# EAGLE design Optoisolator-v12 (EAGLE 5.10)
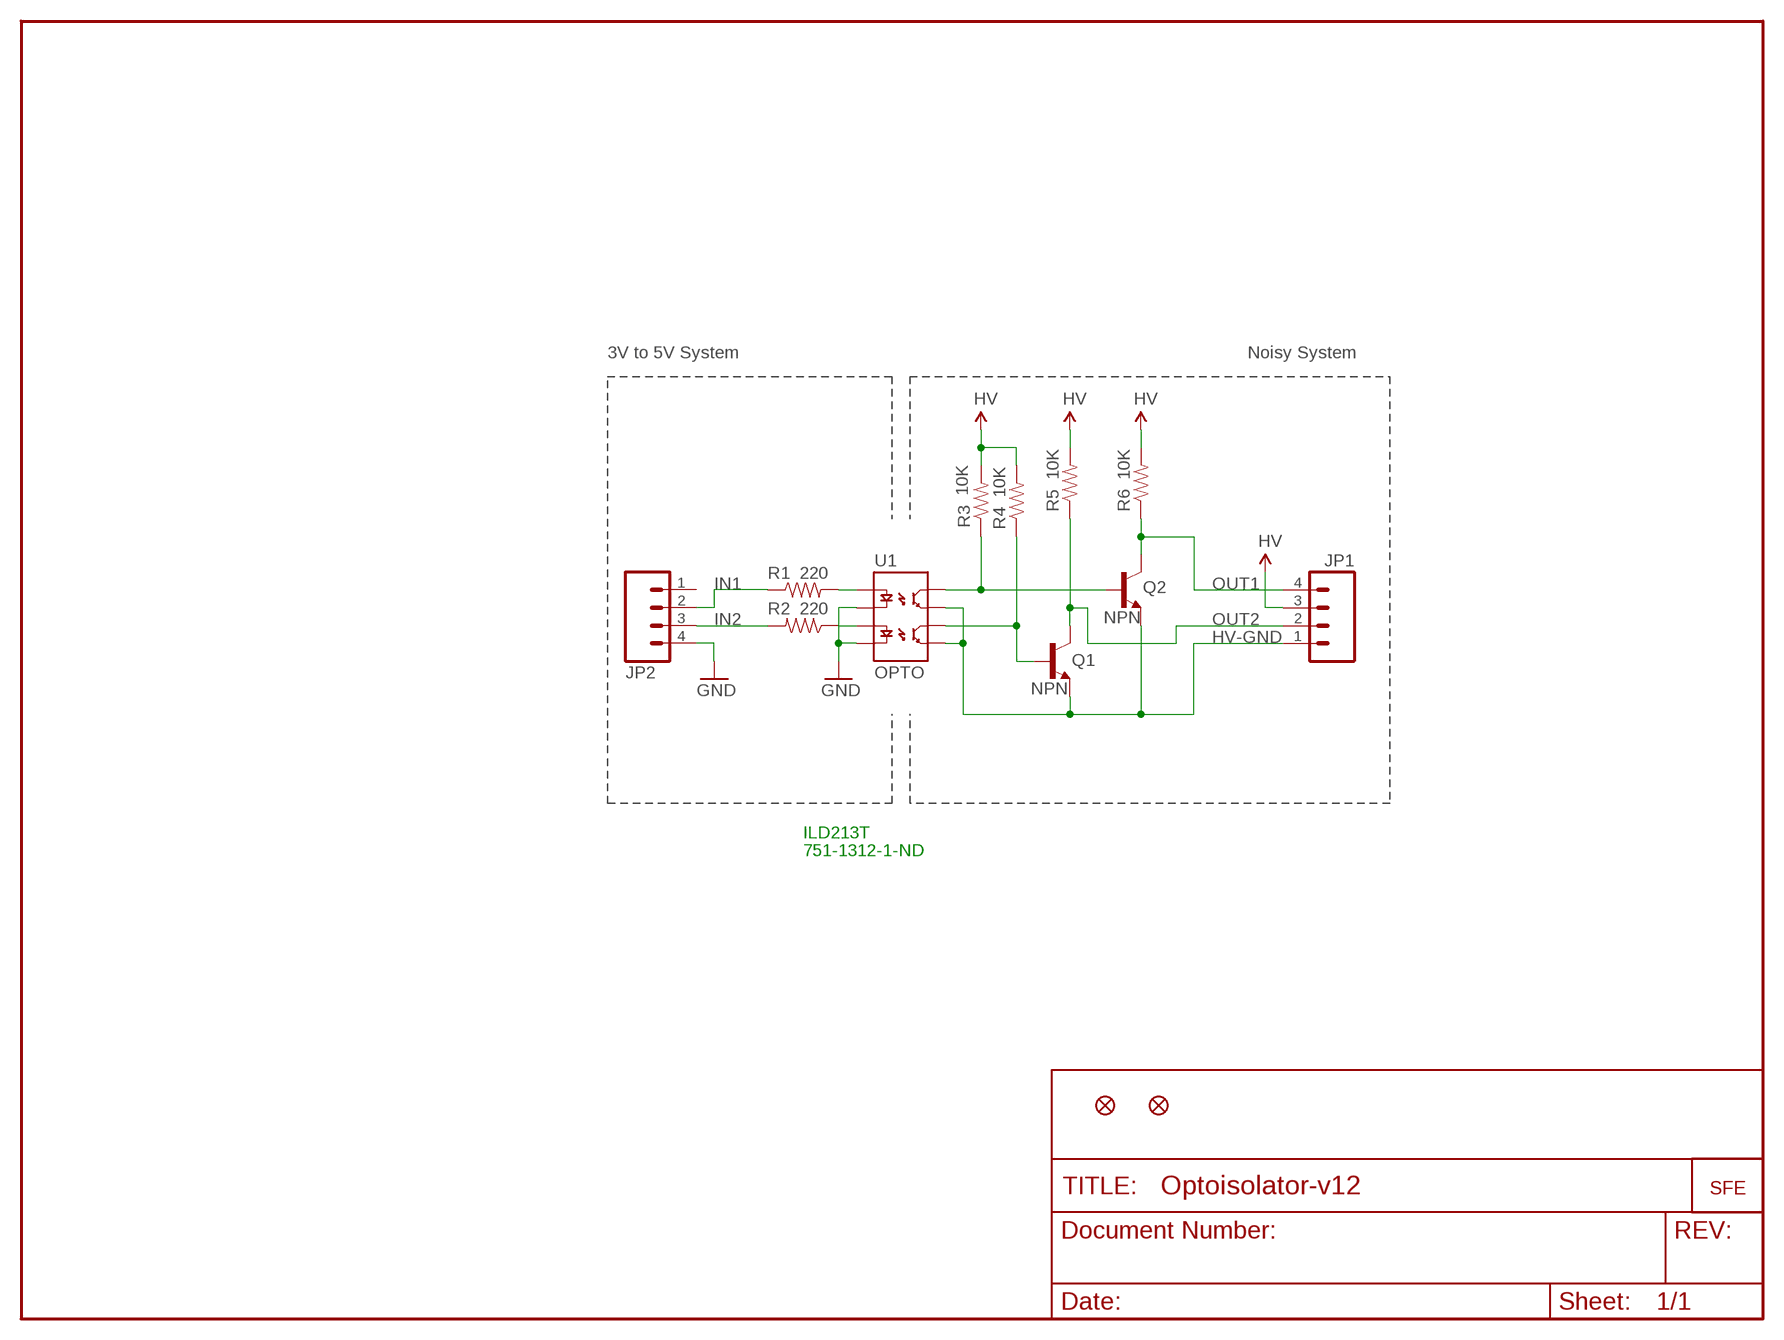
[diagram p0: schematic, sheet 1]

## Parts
JP1  M04PTH  [1X04]
JP2  M04PTH  [1X04]
Q1  NPN  TRANSISTOR_NPNSOT23-3  [SOT23-3]
Q2  NPN  TRANSISTOR_NPNSOT23-3  [SOT23-3]
R1  220  RESISTOR0402  [C0402]
R2  220  RESISTOR0402  [C0402]
R3  10K  RESISTOR0402  [C0402]
R4  10K  RESISTOR0402  [C0402]
R5  10K  RESISTOR0402  [C0402]
R6  10K  RESISTOR0402  [C0402]
U1  OPTO  OPTOISOLATOR-2SOIC8  [SO08-2]
U$1  LOGO-SFESK  [SFE-LOGO-FLAME]
U$2  FIDUCIAL1X2  [FIDUCIAL-1X2]
U$3  FIDUCIAL1X2  [FIDUCIAL-1X2]

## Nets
GND: JP2.4 U1.2(C1) U1.4(C2)
HV-GND: JP1.1 Q1.2(E) Q2.2(E) U1.5(EM2) U1.7(EM1)
IN1: JP2.2 R1.1
IN2: JP2.3 R2.2
N$1: R1.2 U1.1(A1)
N$2: R2.1 U1.3(A2)
OUT1: JP1.4 Q2.3(C) R6.1
OUT1N: Q2.1(B) R3.1 U1.8(CL1)
OUT2: JP1.2 Q1.3(C) R5.1
OUT2N: Q1.1(B) R4.1 U1.6(CL2)
VCC: JP1.3 R3.2 R4.2 R5.2 R6.2 ; supply symbol labelled HV
Unconnected: JP2.1

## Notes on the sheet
- 3V to 5V System | Noisy System
- ILD213T
- 751-1312-1-ND

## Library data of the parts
JP1 JP2 = SparkFun:M04: Header 4 Standard 4-pin 0.1" header. Use with straight break away headers (SKU : PRT-00116), right angle break away headers (PRT-00553), swiss pins (PRT-00743), machine pins (PRT-00117), and female headers (PRT-00115). Molex polarized connector foot print use with SKU : PRT-08231 with associated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
Q1 Q2 = SparkFun:TRANSISTOR_NPN: Transistor NPN BJT configuration in SOT23 package. MMBT2222 is the common NPN we use. Double check BCE configuration again layout.
R1-R6 = SparkFun:RESISTOR: Resistor
U1 = SparkFun:OPTOISOLATOR-2: Description: Dual gate opto isolator. Vishay part : ILD213T
U$1 = SparkFun:LOGO-SFE: Spark Fun Electronics PCB Logo
U$2 U$3 = SparkFun:FIDUCIAL: Fiducial Alignment Points

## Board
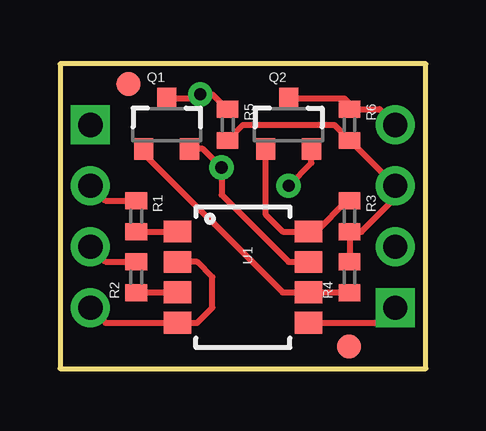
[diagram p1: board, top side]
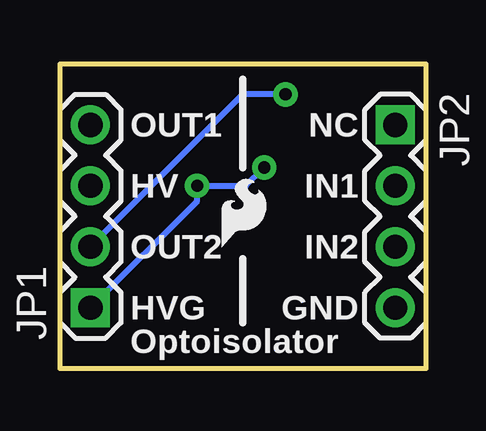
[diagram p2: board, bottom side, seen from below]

Size 15.24 x 12.7 mm. Coordinates in mm from the lower left corner, seen from the top.
Outline: 0,0 15.24,0 15.24,12.7 0,12.7 0,0
Copper layers (1*16): Top 0.035mm / dielectric 1.5mm / Bottom 0.035mm
Design rules "SparkFun *": minimum track width 8mil, minimum drill 20mil, track to track 8mil, track to pad 8mil, pad to pad 8mil, via to via 8mil, smd to smd 8mil, copper to edge 10mil, drill to drill 8mil, minimum pad ring 12mil, minimum via ring 10mil, stop-mask expansion 4mil, vias tented up to drill 20mil, thermal gap 10mil

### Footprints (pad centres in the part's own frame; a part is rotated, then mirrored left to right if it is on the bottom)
1X04 = drill 1.016 square: 1 0,0 | drill 1.016 round: 2 2.54,0; 3 5.08,0; 4 7.62,0
SOT23-3 = smd 0.8 x 0.9: 1 -0.95,-1; 2 0.95,-1; 3 0,1.1
C0402 = smd 0.7 x 0.9: 1 -0.65,0; 2 0.65,0
SO08-2 = smd 0.914 x 1.143: 1 -1.905,-2.731; 2 -0.635,-2.731; 3 0.635,-2.731; 4 1.905,-2.731; 5 1.905,2.731; 6 0.635,2.731; 7 -0.635,2.731; 8 -1.905,2.731
FIDUCIAL-1X2 = smd 1 x 1: 1 0,0

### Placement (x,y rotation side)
JP1  13.97,2.54 90 bottom
JP2  1.27,10.16 270 bottom
Q1  4.45,10.16 0 top
Q2  9.53,10.16 0 top
R1  3.17,6.35 270 top
R2  3.17,3.81 90 top
R3  12.06,6.35 270 top
R4  12.06,3.81 90 top
R5  6.99,10.16 270 top
R6  12.06,10.16 270 top
U1  7.62,3.81 270 top
U$1  8.51,5.08 0 bottom
U$2  2.84,11.86 0 top
U$3  12.04,0.91 0 top

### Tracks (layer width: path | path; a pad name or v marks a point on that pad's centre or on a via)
GND
  Top 0.254: JP2.4 1.91,1.91 U1.4 5.71,1.91 6.35,2.54 6.35,3.81 5.71,4.45 U1.2
HV-GND  (via drill 0.51)
  Top 0.254: U1.7 9.53,4.45 6.73,7.24 v6.73,8.38 5.95,9.16 Q1.2 | U1.5 13.34,1.91 JP1.1 | Q2.2 10.47,8.57 v9.53,7.62
  Bottom 0.254: JP1.1 9.53,6.99 v9.53,7.62 7.49,7.62 v6.73,8.38
IN1
  Top 0.254: R1.1 1.89,7 JP2.2
IN2
  Top 0.254: R2.2 1.89,4.46 JP2.3
N$1
  Top 0.254: R1.2 3.17,5.71 U1.1
N$2
  Top 0.254: R2.1 3.17,3.05 3.3,3.17 U1.3
OUT1
  Top 0.254: Q2.3 11.85,11.26 12.19,10.92 12.08,10.81 R6.1 13.32,10.81 JP1.4
OUT1N
  Top 0.254: R3.1 11.95,7 10.67,5.71 U1.8 9.27,5.71 8.57,6.41 Q2.1
OUT2  (via drill 0.51)
  Top 0.254: R5.1 6.97,10.81 6.35,11.43 v5.84,11.43 5.67,11.26 Q1.3
  Bottom 0.254: JP1.2 7.62,11.43 v5.84,11.43
OUT2N
  Top 0.254: R4.1 11.95,3.16 11.94,3.17 U1.6 9.27,3.17 3.5,8.95 Q1.1
VCC
  Top 0.254: 12.06,4.45 R4.2 R3.2 12.56,5.7 13.97,7.11 JP1.3 12.08,9.51 R6.2 12.06,9.53 11.43,10.16 7.62,10.16 6.99,9.53 R5.2

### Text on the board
bPlace: NC | OUT1 | IN1 | HV | IN2 | OUT2 | GND | HVG | Optoisolator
